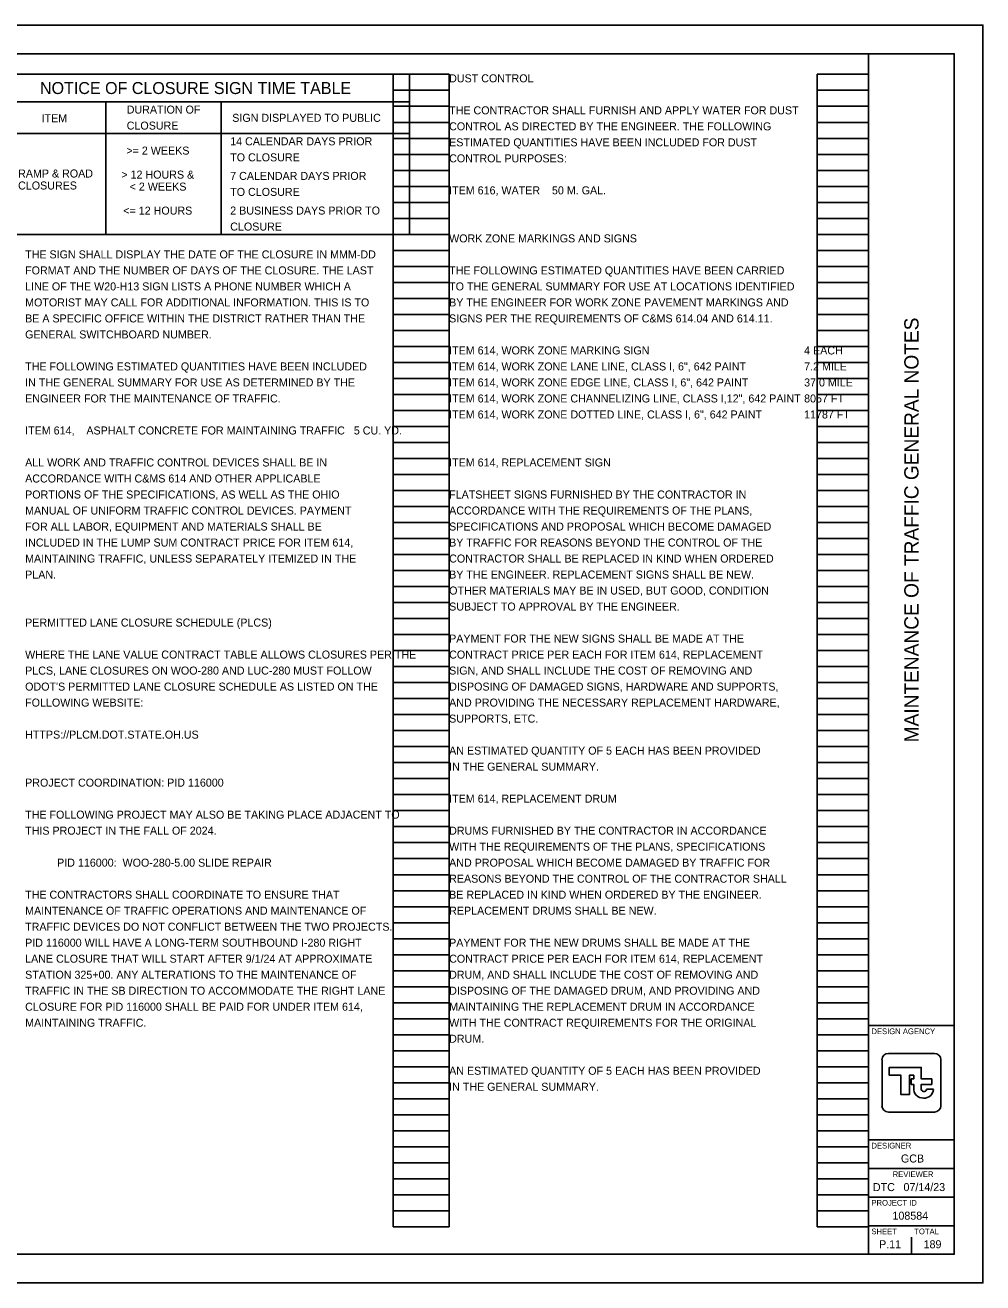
# Model space of a CAD drawing. Extents: x 0 to 34, y 0 to 22.
# Drawn here: x 17.24 to 34, y 0 to 22 of the extents above; entities that cross this region are included whole.
import ezdxf

# ---------------------------------------------------------------- set-up
doc = ezdxf.new("R2010")
doc.units = 0
for name, color, linetype in [('SH_Border', 7, 'Continuous'), ('SH_Cut_Line', 7, 'Continuous'), ('SH_Data', 7, 'Continuous'), ('SH_Text', 7, 'Continuous')]:
    doc.layers.add(name, color=color, linetype=linetype)

msp = doc.modelspace()

# ---------------------------------------------------------------- linework, layer by layer
at = {"layer": 'SH_Border'}
for p, q in [((32, 0.5), (32, 21.5)), ((32, 4.5), (33.5, 4.5)), ((32, 2.5), (33.5, 2.5)), ((32, 2), (33.5, 2)), ((32, 1.5), (33.5, 1.5)), ((32, 1), (33.5, 1))]:
    msp.add_line(p, q, dxfattribs=at)
msp.add_lwpolyline([(1.5, 21.5), (33.5, 21.5), (33.5, 0.5), (1.5, 0.5)], close=True, dxfattribs=at)
at = {"layer": 'SH_Cut_Line'}
msp.add_lwpolyline([(0, 0), (34, 0), (34, 22), (0, 22)], close=True, dxfattribs=at)
at = {"layer": 'SH_Data'}
for p, q in [((23.68, 0.98), (23.68, 21.14)), ((23.68, 21.14), (24.66, 21.14)), ((24.66, 0.98), (24.66, 21.14)), ((31.1, 0.98), (31.1, 21.14)), ((31.1, 21.14), (32, 21.14)), ((32, 0.98), (32, 21.14)), ((23.68, 20.86), (24.66, 20.86)), ((31.1, 20.86), (32, 20.86)), ((23.68, 20.58), (24.66, 20.58)), ((31.1, 20.58), (32, 20.58)), ((23.68, 20.3), (24.66, 20.3)), ((31.1, 20.3), (32, 20.3)), ((23.68, 20.02), (24.66, 20.02)), ((31.1, 20.02), (32, 20.02)), ((23.68, 19.74), (24.66, 19.74)), ((31.1, 19.74), (32, 19.74)), ((23.68, 19.46), (24.66, 19.46)), ((31.1, 19.46), (32, 19.46)), ((23.68, 19.18), (24.66, 19.18)), ((31.1, 19.18), (32, 19.18)), ((23.68, 18.9), (24.66, 18.9)), ((31.1, 18.9), (32, 18.9)), ((23.68, 18.62), (24.66, 18.62)), ((31.1, 18.62), (32, 18.62)), ((23.68, 18.34), (24.66, 18.34)), ((31.1, 18.34), (32, 18.34)), ((23.68, 18.06), (24.66, 18.06)), ((31.1, 18.06), (32, 18.06)), ((23.68, 17.78), (24.66, 17.78)), ((31.1, 17.78), (32, 17.78)), ((23.68, 17.5), (24.66, 17.5)), ((31.1, 17.5), (32, 17.5)), ((23.68, 17.22), (24.66, 17.22)), ((31.1, 17.22), (32, 17.22)), ((23.68, 16.94), (24.66, 16.94)), ((31.1, 16.94), (32, 16.94)), ((23.68, 16.66), (24.66, 16.66)), ((31.1, 16.66), (32, 16.66)), ((23.68, 16.38), (24.66, 16.38)), ((31.1, 16.38), (32, 16.38)), ((23.68, 16.1), (24.66, 16.1)), ((31.1, 16.1), (32, 16.1)), ((23.68, 15.82), (24.66, 15.82)), ((31.1, 15.82), (32, 15.82)), ((23.68, 15.54), (24.66, 15.54)), ((31.1, 15.54), (32, 15.54)), ((23.68, 15.26), (24.66, 15.26)), ((31.1, 15.26), (32, 15.26)), ((23.68, 14.98), (24.66, 14.98)), ((31.1, 14.98), (32, 14.98)), ((23.68, 14.7), (24.66, 14.7)), ((31.1, 14.7), (32, 14.7)), ((23.68, 14.42), (24.66, 14.42)), ((31.1, 14.42), (32, 14.42)), ((23.68, 14.14), (24.66, 14.14)), ((31.1, 14.14), (32, 14.14)), ((23.68, 13.86), (24.66, 13.86)), ((31.1, 13.86), (32, 13.86)), ((23.68, 13.58), (24.66, 13.58)), ((31.1, 13.58), (32, 13.58)), ((23.68, 13.3), (24.66, 13.3)), ((31.1, 13.3), (32, 13.3)), ((23.68, 13.02), (24.66, 13.02)), ((31.1, 13.02), (32, 13.02)), ((23.68, 12.74), (24.66, 12.74)), ((31.1, 12.74), (32, 12.74)), ((23.68, 12.46), (24.66, 12.46)), ((31.1, 12.46), (32, 12.46)), ((23.68, 12.18), (24.66, 12.18)), ((31.1, 12.18), (32, 12.18)), ((23.68, 11.9), (24.66, 11.9)), ((31.1, 11.9), (32, 11.9)), ((23.68, 11.62), (24.66, 11.62)), ((31.1, 11.62), (32, 11.62)), ((23.68, 11.34), (24.66, 11.34)), ((31.1, 11.34), (32, 11.34)), ((23.68, 11.06), (24.66, 11.06)), ((31.1, 11.06), (32, 11.06)), ((23.68, 10.78), (24.66, 10.78)), ((31.1, 10.78), (32, 10.78)), ((23.68, 10.5), (24.66, 10.5)), ((31.1, 10.5), (32, 10.5)), ((23.68, 10.22), (24.66, 10.22)), ((31.1, 10.22), (32, 10.22)), ((23.68, 9.94), (24.66, 9.94)), ((31.1, 9.94), (32, 9.94)), ((23.68, 9.66), (24.66, 9.66)), ((31.1, 9.66), (32, 9.66)), ((23.68, 9.38), (24.66, 9.38)), ((31.1, 9.38), (32, 9.38)), ((23.68, 9.1), (24.66, 9.1)), ((31.1, 9.1), (32, 9.1)), ((23.68, 8.82), (24.66, 8.82)), ((31.1, 8.82), (32, 8.82)), ((23.68, 8.54), (24.66, 8.54)), ((31.1, 8.54), (32, 8.54)), ((23.68, 8.26), (24.66, 8.26)), ((31.1, 8.26), (32, 8.26)), ((23.68, 7.98), (24.66, 7.98)), ((31.1, 7.98), (32, 7.98)), ((23.68, 7.7), (24.66, 7.7)), ((31.1, 7.7), (32, 7.7)), ((23.68, 7.42), (24.66, 7.42)), ((31.1, 7.42), (32, 7.42)), ((23.68, 7.14), (24.66, 7.14)), ((31.1, 7.14), (32, 7.14)), ((23.68, 6.86), (24.66, 6.86)), ((31.1, 6.86), (32, 6.86)), ((23.68, 6.58), (24.66, 6.58)), ((31.1, 6.58), (32, 6.58)), ((23.68, 6.3), (24.66, 6.3)), ((31.1, 6.3), (32, 6.3)), ((23.68, 6.02), (24.66, 6.02)), ((31.1, 6.02), (32, 6.02)), ((23.68, 5.74), (24.66, 5.74)), ((31.1, 5.74), (32, 5.74)), ((23.68, 5.46), (24.66, 5.46)), ((31.1, 5.46), (32, 5.46)), ((23.68, 5.18), (24.66, 5.18)), ((31.1, 5.18), (32, 5.18)), ((23.68, 4.9), (24.66, 4.9)), ((31.1, 4.9), (32, 4.9)), ((23.68, 4.62), (24.66, 4.62)), ((31.1, 4.62), (32, 4.62)), ((23.68, 4.34), (24.66, 4.34)), ((31.1, 4.34), (32, 4.34)), ((23.68, 4.06), (24.66, 4.06)), ((31.1, 4.06), (32, 4.06)), ((23.68, 3.78), (24.66, 3.78)), ((31.1, 3.78), (32, 3.78)), ((23.68, 3.5), (24.66, 3.5)), ((31.1, 3.5), (32, 3.5)), ((32.75, 3.5), (32.75, 3.5)), ((32.791, 3.415), (32.791, 3.415)), ((33.136, 3.385), (33.015, 3.385)), ((23.68, 3.22), (24.66, 3.22)), ((31.1, 3.22), (32, 3.22)), ((23.68, 2.94), (24.66, 2.94)), ((31.1, 2.94), (32, 2.94)), ((23.68, 2.66), (24.66, 2.66)), ((31.1, 2.66), (32, 2.66)), ((23.68, 2.38), (24.66, 2.38)), ((31.1, 2.38), (32, 2.38)), ((23.68, 2.1), (24.66, 2.1)), ((31.1, 2.1), (32, 2.1)), ((23.68, 1.82), (24.66, 1.82)), ((31.1, 1.82), (32, 1.82)), ((23.68, 1.54), (24.66, 1.54)), ((31.1, 1.54), (32, 1.54)), ((23.68, 1.26), (24.66, 1.26)), ((31.1, 1.26), (32, 1.26)), ((23.68, 0.98), (24.66, 0.98)), ((31.1, 0.98), (32, 0.98)), ((32.375, 0.675), (32.375, 0.675)), ((32.75, 0.5), (32.75, 0.8))]:
    msp.add_line(p, q, dxfattribs=at)
for points in [[(32.348, 4.014), (33.152, 4.014)], [(32.236, 3.099), (32.236, 3.901)], [(32.922, 3.399), (32.922, 3.47), (33.107, 3.47), (33.107, 3.568), (32.922, 3.568), (32.922, 3.768), (32.361, 3.768), (32.361, 3.632), (32.566, 3.632), (32.566, 3.294), (32.715, 3.294), (32.715, 3.63), (32.79, 3.63), (32.79, 3.568), (32.748, 3.568), (32.748, 3.47), (32.79, 3.47), (32.79, 3.415), (32.791, 3.415)], [(33.264, 3.901), (33.264, 3.099)], [(33.152, 2.986), (32.348, 2.986)]]:
    msp.add_lwpolyline(points, dxfattribs=at)
for centre, radius, start, end in [((32.348, 3.901), 0.113, 90, 180), ((33.152, 3.901), 0.113, 360, 90), ((32.949, 3.392), 0.16, 171.8856, 274.8323), ((32.968, 3.392), 0.0473, 171.8856, 350.9243), ((32.976, 3.392), 0.16, 265.1677, 357.3201), ((32.348, 3.099), 0.113, 180, 270), ((33.152, 3.099), 0.113, 270, 360)]:
    msp.add_arc(centre, radius, start, end, dxfattribs=at)
at = {"layer": 'SH_Text'}
for p, q in [((16.947, 21.14), (23.966, 21.14)), ((23.966, 21.14), (23.966, 18.34)), ((16.947, 20.66), (23.966, 20.66)), ((18.652, 20.66), (18.652, 18.34)), ((20.67, 20.66), (20.67, 18.34)), ((16.947, 20.106), (23.966, 20.106)), ((16.947, 18.34), (23.966, 18.34))]:
    msp.add_line(p, q, dxfattribs=at)

# ---------------------------------------------------------------- texts
at = {"layer": 'SH_Data'}
msp.add_text('MAINTENANCE OF TRAFFIC GENERAL NOTES', height=0.25, rotation=90, dxfattribs=at).set_placement((32.875, 9.455))
for s, height, p in [('DESIGN AGENCY', 0.1, (32.05, 4.35)), ('DESIGNER', 0.1, (32.05, 2.35)), ('GCB', 0.14, (32.566, 2.105)), ('REVIEWER', 0.1, (32.422, 1.85)), ('DTC', 0.14, (32.076, 1.605)), ('07/14/23', 0.14, (32.611, 1.605)), ('PROJECT ID', 0.1, (32.05, 1.35)), ('108584', 0.14, (32.418, 1.105)), ('SHEET', 0.1, (32.05, 0.85)), ('TOTAL', 0.1, (32.8, 0.85)), ('P.11', 0.14, (32.184, 0.605)), ('189', 0.14, (32.963, 0.605))]:
    msp.add_text(s, height=height, dxfattribs=at).set_placement(p)
at = {"layer": 'SH_Text'}
for s, height, p in [('DUST CONTROL', 0.14, (24.66, 21)), ('NOTICE OF CLOSURE SIGN TIME TABLE', 0.21, (17.5, 20.795)), ('DURATION OF ', 0.14, (19.018, 20.453)), ('THE CONTRACTOR SHALL FURNISH AND APPLY WATER FOR DUST', 0.14, (24.66, 20.44)), ('ITEM', 0.14, (17.527, 20.301)), ('CLOSURE', 0.14, (19.018, 20.173)), ('SIGN DISPLAYED TO PUBLIC', 0.14, (20.864, 20.309)), ('CONTROL AS DIRECTED BY THE ENGINEER. THE FOLLOWING', 0.14, (24.66, 20.16)), ('14 CALENDAR DAYS PRIOR ', 0.14, (20.829, 19.898)), ('ESTIMATED QUANTITIES HAVE BEEN INCLUDED FOR DUST', 0.14, (24.66, 19.88)), ('>= 2 WEEKS', 0.14, (19.012, 19.736)), ('TO CLOSURE', 0.14, (20.829, 19.618)), ('CONTROL PURPOSES:', 0.14, (24.66, 19.6)), ('RAMP & ROAD', 0.14, (17.117, 19.335)), ('> 12 HOURS & ', 0.14, (18.924, 19.316)), ('7 CALENDAR DAYS PRIOR ', 0.14, (20.829, 19.293)), ('CLOSURES', 0.14, (17.117, 19.125)), ('< 2 WEEKS', 0.14, (19.069, 19.106)), ('TO CLOSURE', 0.14, (20.829, 19.013)), ('ITEM 616, WATER    50 M. GAL.', 0.14, (24.66, 19.04)), ('<= 12 HOURS', 0.14, (18.958, 18.686)), ('2 BUSINESS DAYS PRIOR TO ', 0.14, (20.829, 18.687)), ('CLOSURE', 0.14, (20.829, 18.407)), ('WORK ZONE MARKINGS AND SIGNS', 0.14, (24.66, 18.2)), ('THE SIGN SHALL DISPLAY THE DATE OF THE CLOSURE IN MMM-DD', 0.14, (17.24, 17.92)), ('FORMAT AND THE NUMBER OF DAYS OF THE CLOSURE. THE LAST', 0.14, (17.24, 17.64)), ('THE FOLLOWING ESTIMATED QUANTITIES HAVE BEEN CARRIED', 0.14, (24.66, 17.64)), ('LINE OF THE W20-H13 SIGN LISTS A PHONE NUMBER WHICH A', 0.14, (17.24, 17.36)), ('TO THE GENERAL SUMMARY FOR USE AT LOCATIONS IDENTIFIED', 0.14, (24.66, 17.36)), ('MOTORIST MAY CALL FOR ADDITIONAL INFORMATION. THIS IS TO', 0.14, (17.24, 17.08)), ('BY THE ENGINEER FOR WORK ZONE PAVEMENT MARKINGS AND', 0.14, (24.66, 17.08)), ('BE A SPECIFIC OFFICE WITHIN THE DISTRICT RATHER THAN THE', 0.14, (17.24, 16.8)), ('SIGNS PER THE REQUIREMENTS OF C&MS 614.04 AND 614.11.', 0.14, (24.66, 16.8)), ('GENERAL SWITCHBOARD NUMBER.', 0.14, (17.24, 16.52)), ('ITEM 614, WORK ZONE MARKING SIGN', 0.14, (24.66, 16.24)), (' 4 EACH', 0.14, (30.82, 16.24)), ('THE FOLLOWING ESTIMATED QUANTITIES HAVE BEEN INCLUDED', 0.14, (17.24, 15.96)), ('ITEM 614, WORK ZONE LANE LINE, CLASS I, 6", 642 PAINT', 0.14, (24.66, 15.96)), (' 7.2 MILE', 0.14, (30.82, 15.96)), ('IN THE GENERAL SUMMARY FOR USE AS DETERMINED BY THE', 0.14, (17.24, 15.68)), ('ITEM 614, WORK ZONE EDGE LINE, CLASS I, 6", 642 PAINT', 0.14, (24.66, 15.68)), (' 37.0 MILE', 0.14, (30.82, 15.68)), ('ENGINEER FOR THE MAINTENANCE OF TRAFFIC.', 0.14, (17.24, 15.4)), ('ITEM 614, WORK ZONE CHANNELIZING LINE, CLASS I,12", 642 PAINT', 0.14, (24.66, 15.4)), (' 8057 FT', 0.14, (30.82, 15.4)), ('ITEM 614, WORK ZONE DOTTED LINE, CLASS I, 6", 642 PAINT', 0.14, (24.66, 15.12)), (' 11787 FT', 0.14, (30.82, 15.12)), ('ITEM 614,    ASPHALT CONCRETE FOR MAINTAINING TRAFFIC   5 CU. YD.', 0.14, (17.24, 14.84)), ('ALL WORK AND TRAFFIC CONTROL DEVICES SHALL BE IN', 0.14, (17.24, 14.28)), ('ITEM 614, REPLACEMENT SIGN', 0.14, (24.66, 14.28)), ('ACCORDANCE WITH C&MS 614 AND OTHER APPLICABLE', 0.14, (17.24, 14)), ('PORTIONS OF THE SPECIFICATIONS, AS WELL AS THE OHIO', 0.14, (17.24, 13.72)), ('FLATSHEET SIGNS FURNISHED BY THE CONTRACTOR IN', 0.14, (24.66, 13.72)), ('MANUAL OF UNIFORM TRAFFIC CONTROL DEVICES. PAYMENT', 0.14, (17.24, 13.44)), ('ACCORDANCE WITH THE REQUIREMENTS OF THE PLANS,', 0.14, (24.66, 13.44)), ('FOR ALL LABOR, EQUIPMENT AND MATERIALS SHALL BE', 0.14, (17.24, 13.16)), ('SPECIFICATIONS AND PROPOSAL WHICH BECOME DAMAGED', 0.14, (24.66, 13.16)), ('INCLUDED IN THE LUMP SUM CONTRACT PRICE FOR ITEM 614,', 0.14, (17.24, 12.88)), ('BY TRAFFIC FOR REASONS BEYOND THE CONTROL OF THE', 0.14, (24.66, 12.88)), ('MAINTAINING TRAFFIC, UNLESS SEPARATELY ITEMIZED IN THE', 0.14, (17.24, 12.6)), ('CONTRACTOR SHALL BE REPLACED IN KIND WHEN ORDERED', 0.14, (24.66, 12.6)), ('PLAN.', 0.14, (17.24, 12.32)), ('BY THE ENGINEER. REPLACEMENT SIGNS SHALL BE NEW.', 0.14, (24.66, 12.32)), ('OTHER MATERIALS MAY BE IN USED, BUT GOOD, CONDITION', 0.14, (24.66, 12.04)), ('SUBJECT TO APPROVAL BY THE ENGINEER.', 0.14, (24.66, 11.76)), ('PERMITTED LANE CLOSURE SCHEDULE (PLCS)', 0.14, (17.24, 11.48)), ('PAYMENT FOR THE NEW SIGNS SHALL BE MADE AT THE', 0.14, (24.66, 11.2)), ('WHERE THE LANE VALUE CONTRACT TABLE ALLOWS CLOSURES PER THE ', 0.14, (17.24, 10.92)), ('CONTRACT PRICE PER EACH FOR ITEM 614, REPLACEMENT', 0.14, (24.66, 10.92)), ('PLCS, LANE CLOSURES ON WOO-280 AND LUC-280 MUST FOLLOW ', 0.14, (17.24, 10.64)), ('SIGN, AND SHALL INCLUDE THE COST OF REMOVING AND', 0.14, (24.66, 10.64)), ("ODOT'S PERMITTED LANE CLOSURE SCHEDULE AS LISTED ON THE ", 0.14, (17.24, 10.36)), ('DISPOSING OF DAMAGED SIGNS, HARDWARE AND SUPPORTS,', 0.14, (24.66, 10.36)), ('FOLLOWING WEBSITE:', 0.14, (17.24, 10.08)), ('AND PROVIDING THE NECESSARY REPLACEMENT HARDWARE,', 0.14, (24.66, 10.08)), ('SUPPORTS, ETC.', 0.14, (24.66, 9.8)), ('HTTPS://PLCM.DOT.STATE.OH.US', 0.14, (17.24, 9.52)), ('AN ESTIMATED QUANTITY OF 5 EACH HAS BEEN PROVIDED', 0.14, (24.66, 9.24)), ('IN THE GENERAL SUMMARY.', 0.14, (24.66, 8.96)), ('PROJECT COORDINATION: PID 116000', 0.14, (17.24, 8.68)), ('ITEM 614, REPLACEMENT DRUM', 0.14, (24.66, 8.4)), ('THE FOLLOWING PROJECT MAY ALSO BE TAKING PLACE ADJACENT TO', 0.14, (17.24, 8.12)), ('THIS PROJECT IN THE FALL OF 2024.', 0.14, (17.24, 7.84)), ('DRUMS FURNISHED BY THE CONTRACTOR IN ACCORDANCE', 0.14, (24.66, 7.84)), ('WITH THE REQUIREMENTS OF THE PLANS, SPECIFICATIONS', 0.14, (24.66, 7.56)), ('PID 116000:  WOO-280-5.00 SLIDE REPAIR', 0.14, (17.8, 7.28)), ('AND PROPOSAL WHICH BECOME DAMAGED BY TRAFFIC FOR', 0.14, (24.66, 7.28)), ('REASONS BEYOND THE CONTROL OF THE CONTRACTOR SHALL', 0.14, (24.66, 7)), ('THE CONTRACTORS SHALL COORDINATE TO ENSURE THAT ', 0.14, (17.24, 6.72)), ('BE REPLACED IN KIND WHEN ORDERED BY THE ENGINEER.', 0.14, (24.66, 6.72)), ('MAINTENANCE OF TRAFFIC OPERATIONS AND MAINTENANCE OF ', 0.14, (17.24, 6.44)), ('REPLACEMENT DRUMS SHALL BE NEW.', 0.14, (24.66, 6.44)), ('TRAFFIC DEVICES DO NOT CONFLICT BETWEEN THE TWO PROJECTS. ', 0.14, (17.24, 6.16)), ('PID 116000 WILL HAVE A LONG-TERM SOUTHBOUND I-280 RIGHT ', 0.14, (17.24, 5.88)), ('PAYMENT FOR THE NEW DRUMS SHALL BE MADE AT THE', 0.14, (24.66, 5.88)), ('LANE CLOSURE THAT WILL START AFTER 9/1/24 AT APPROXIMATE ', 0.14, (17.24, 5.6)), ('CONTRACT PRICE PER EACH FOR ITEM 614, REPLACEMENT', 0.14, (24.66, 5.6)), ('STATION 325+00. ANY ALTERATIONS TO THE MAINTENANCE OF ', 0.14, (17.24, 5.32)), ('DRUM, AND SHALL INCLUDE THE COST OF REMOVING AND', 0.14, (24.66, 5.32)), ('TRAFFIC IN THE SB DIRECTION TO ACCOMMODATE THE RIGHT LANE ', 0.14, (17.24, 5.04)), ('DISPOSING OF THE DAMAGED DRUM, AND PROVIDING AND', 0.14, (24.66, 5.04)), ('CLOSURE FOR PID 116000 SHALL BE PAID FOR UNDER ITEM 614, ', 0.14, (17.24, 4.76)), ('MAINTAINING THE REPLACEMENT DRUM IN ACCORDANCE', 0.14, (24.66, 4.76)), ('MAINTAINING TRAFFIC.', 0.14, (17.24, 4.48)), ('WITH THE CONTRACT REQUIREMENTS FOR THE ORIGINAL', 0.14, (24.66, 4.48)), ('DRUM.', 0.14, (24.66, 4.2)), ('AN ESTIMATED QUANTITY OF 5 EACH HAS BEEN PROVIDED', 0.14, (24.66, 3.64)), ('IN THE GENERAL SUMMARY.', 0.14, (24.66, 3.36))]:
    msp.add_text(s, height=height, dxfattribs=at).set_placement(p)

doc.saveas('drawing.dxf')
